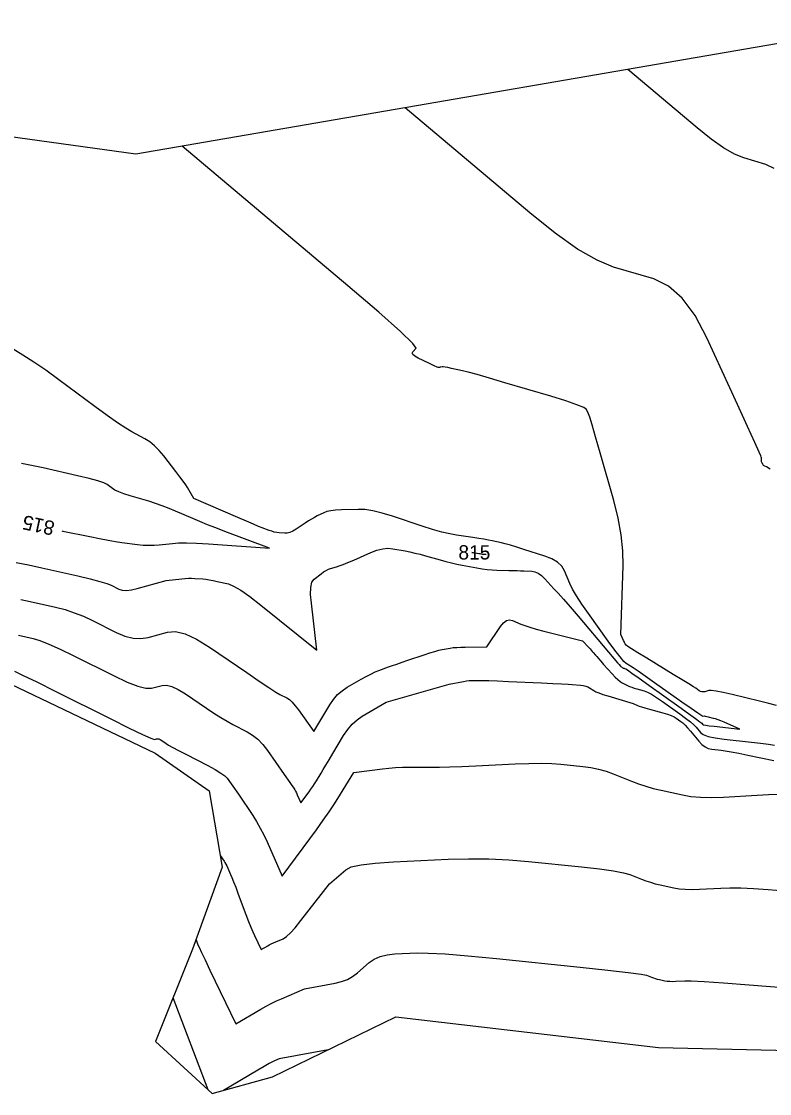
# Model space of a CAD drawing. Extents: x 1715724 to 1716561, y 394063 to 395906.
# Drawn here: x 1716062.2 to 1716135.4, y 394616.2 to 394721.1 of the extents above; entities that cross this region are included whole.
import ezdxf

# ---------------------------------------------------------------- set-up
doc = ezdxf.new("R2010")
doc.units = 0
for name, color, linetype in [('DT_X_Contour_Major', 7, 'Continuous'), ('DT_X_Contour_Minor', 7, 'Continuous'), ('DT_X_TIN_Hull', 7, 'Continuous')]:
    doc.layers.add(name, color=color, linetype=linetype)

msp = doc.modelspace()

# ---------------------------------------------------------------- linework, layer by layer
at = {"layer": 'DT_X_Contour_Major'}
for points in [[(1716066.17, 394671.24), (1716066.28, 394671.22), (1716068.92, 394670.67), (1716069.86, 394670.48), (1716070.7, 394670.32), (1716071.43, 394670.19), (1716072.05, 394670.1), (1716073.58, 394669.9), (1716074.15, 394669.85), (1716074.69, 394669.82), (1716075.21, 394669.83), (1716075.71, 394669.86), (1716077.01, 394670.01), (1716077.59, 394670.05), (1716078.38, 394670.05), (1716079.36, 394670.02), (1716080.54, 394669.95), (1716086.5, 394669.55), (1716082.14, 394671.18), (1716081.24, 394671.52), (1716080.42, 394671.84), (1716079.67, 394672.14), (1716079, 394672.43), (1716077.31, 394673.17), (1716076.67, 394673.43), (1716076.01, 394673.68), (1716075.35, 394673.91), (1716074.68, 394674.13), (1716072.87, 394674.67), (1716072.25, 394674.87), (1716071.76, 394675.05), (1716071.38, 394675.22), (1716071.13, 394675.37), (1716070.62, 394675.76), (1716070.3, 394675.92), (1716069.71, 394676.12), (1716068.85, 394676.35), (1716067.72, 394676.62), (1716064.37, 394677.39), (1716063.21, 394677.64), (1716062.22, 394677.84)], [(1716106.3, 394669.13), (1716107.23, 394668.99), (1716107.44, 394668.96), (1716107.5, 394668.95), (1716107.7, 394668.91), (1716107.51, 394668.91), (1716107.47, 394668.91), (1716107.44, 394668.91), (1716107.42, 394668.91), (1716107.4, 394668.92), (1716107.38, 394668.92), (1716107.37, 394668.92), (1716107.36, 394668.93), (1716107.35, 394668.93), (1716107.34, 394668.93), (1716107.31, 394668.94), (1716107.28, 394668.94), (1716107.22, 394668.96), (1716107.12, 394668.97), (1716106.99, 394669), (1716106.3, 394669.13)], [(1716081.68, 394639.46), (1716082.05, 394638.91), (1716082.14, 394638.78), (1716082.22, 394638.62), (1716082.32, 394638.43), (1716082.42, 394638.21), (1716082.69, 394637.6), (1716082.81, 394637.31), (1716082.98, 394636.89), (1716083.19, 394636.34), (1716083.44, 394635.66), (1716084.18, 394633.69), (1716084.44, 394633.01), (1716084.67, 394632.44), (1716084.86, 394631.97), (1716085.02, 394631.62), (1716085.69, 394630.24), (1716086.33, 394630.62), (1716086.48, 394630.7), (1716086.67, 394630.8), (1716086.88, 394630.9), (1716087.13, 394631.01), (1716087.84, 394631.31), (1716088.15, 394631.51), (1716088.54, 394631.87), (1716089.01, 394632.39), (1716089.57, 394633.08), (1716092.37, 394636.68), (1716093.95, 394638.06), (1716094.49, 394638.33), (1716095.46, 394638.55), (1716096.84, 394638.72), (1716098.63, 394638.84), (1716103.97, 394639.09), (1716105.96, 394639.14), (1716107.94, 394639.13), (1716109.91, 394639.04), (1716111.85, 394638.87), (1716117.02, 394638.34), (1716118.77, 394638.15), (1716120.14, 394637.96), (1716121.14, 394637.77), (1716121.75, 394637.6), (1716122.88, 394637.14), (1716123.32, 394636.97), (1716123.77, 394636.83), (1716124.24, 394636.69), (1716124.72, 394636.58), (1716126.04, 394636.29), (1716126.57, 394636.2), (1716127.17, 394636.15), (1716127.84, 394636.13), (1716128.58, 394636.16), (1716130.66, 394636.27), (1716131.54, 394636.3), (1716132.6, 394636.28), (1716133.85, 394636.22), (1716135.28, 394636.12), (1716139.36, 394635.8)]]:
    msp.add_lwpolyline(points, dxfattribs=at)
at = {"layer": 'DT_X_Contour_Minor'}
for points in [[(1716135.87, 394706.72), (1716135.07, 394707.11), (1716132.89, 394707.76), (1716131.99, 394708.12), (1716130.93, 394708.73), (1716129.72, 394709.59), (1716128.34, 394710.69), (1716121.56, 394716.41)], [(1716135.47, 394677.28), (1716135.11, 394677.5), (1716134.95, 394677.57), (1716134.89, 394677.6), (1716134.84, 394677.64), (1716134.8, 394677.69), (1716134.77, 394677.74), (1716134.69, 394677.89), (1716134.66, 394677.94), (1716134.64, 394678), (1716134.63, 394678.05), (1716134.63, 394678.1), (1716134.63, 394678.24), (1716134.63, 394678.29), (1716134.63, 394678.35), (1716134.62, 394678.4), (1716134.6, 394678.45), (1716134.56, 394678.59), (1716134.41, 394678.94), (1716133.98, 394679.89), (1716133.27, 394681.44), (1716132.29, 394683.59), (1716129.3, 394690.12), (1716128.13, 394692.31), (1716126.87, 394694.01), (1716125.53, 394695.2), (1716124.1, 394695.89), (1716120.15, 394697.06), (1716118.54, 394697.72), (1716116.63, 394698.82), (1716114.44, 394700.37), (1716111.97, 394702.35), (1716099.76, 394712.66)], [(1716136.1, 394654.14), (1716135.35, 394654.34), (1716134.44, 394654.57), (1716131.76, 394655.21), (1716130.87, 394655.42), (1716130.19, 394655.55), (1716129.72, 394655.61), (1716129.47, 394655.61), (1716129.08, 394655.49), (1716128.94, 394655.47), (1716128.8, 394655.47), (1716128.67, 394655.51), (1716128.54, 394655.58), (1716128.2, 394655.82), (1716127.97, 394655.97), (1716127.53, 394656.25), (1716126.87, 394656.65), (1716126, 394657.18), (1716123.4, 394658.76), (1716122.54, 394659.29), (1716121.92, 394659.68), (1716121.54, 394659.93), (1716121.38, 394660.04), (1716121.3, 394660.16), (1716121.26, 394660.22), (1716121.22, 394660.29), (1716121.18, 394660.39), (1716121.13, 394660.51), (1716120.88, 394661.1), (1716121.09, 394667.8), (1716121.07, 394669.28), (1716120.91, 394670.84), (1716120.61, 394672.47), (1716120.18, 394674.19), (1716118.85, 394678.88), (1716118.4, 394680.44), (1716118.06, 394681.6), (1716117.83, 394682.35), (1716117.71, 394682.7), (1716117.52, 394683.1), (1716117.25, 394683.3), (1716116.58, 394683.58), (1716115.5, 394683.95), (1716114.02, 394684.41), (1716109.53, 394685.74), (1716108.01, 394686.19), (1716106.81, 394686.53), (1716105.93, 394686.77), (1716105.37, 394686.91), (1716104.31, 394687.14), (1716103.96, 394687.22), (1716103.69, 394687.27), (1716103.5, 394687.29), (1716103.39, 394687.29), (1716103.21, 394687.25), (1716103.15, 394687.23), (1716103.1, 394687.23), (1716103.05, 394687.23), (1716103.01, 394687.24), (1716102.91, 394687.26), (1716102.83, 394687.3), (1716102.67, 394687.37), (1716102.41, 394687.49), (1716102.07, 394687.65), (1716101.05, 394688.15), (1716100.73, 394688.33), (1716100.53, 394688.49), (1716100.47, 394688.64), (1716100.53, 394688.77), (1716100.86, 394689.11), (1716100.53, 394689.58), (1716099.31, 394690.76), (1716097.18, 394692.64), (1716094.16, 394695.22), (1716077.95, 394708.9)], [(1716061.71, 394668.14), (1716062.93, 394667.91), (1716064.22, 394667.63), (1716067.76, 394666.82), (1716068.96, 394666.53), (1716069.9, 394666.29), (1716070.58, 394666.09), (1716071, 394665.92), (1716071.76, 394665.54), (1716072.09, 394665.43), (1716072.5, 394665.41), (1716072.99, 394665.46), (1716073.55, 394665.59), (1716076.38, 394666.37), (1716077.93, 394666.55), (1716078.26, 394666.58), (1716078.57, 394666.59), (1716078.88, 394666.59), (1716079.18, 394666.58), (1716079.96, 394666.53), (1716080.27, 394666.5), (1716080.6, 394666.45), (1716080.97, 394666.38), (1716081.37, 394666.29), (1716082.48, 394666.04), (1716082.99, 394665.83), (1716083.69, 394665.42), (1716084.58, 394664.8), (1716085.66, 394663.96), (1716091.14, 394659.57), (1716090.59, 394664.14), (1716090.51, 394665.02), (1716090.54, 394665.7), (1716090.65, 394666.2), (1716090.86, 394666.5), (1716091.54, 394667.04), (1716091.79, 394667.22), (1716092.03, 394667.37), (1716092.26, 394667.48), (1716092.48, 394667.56), (1716093.06, 394667.71), (1716093.32, 394667.8), (1716093.69, 394667.94), (1716094.16, 394668.13), (1716094.74, 394668.38), (1716096.4, 394669.11), (1716097.01, 394669.34), (1716097.57, 394669.48), (1716098.09, 394669.53), (1716098.56, 394669.49), (1716099.77, 394669.27), (1716100.24, 394669.17), (1716100.73, 394669.06), (1716101.23, 394668.94), (1716101.77, 394668.8), (1716103.21, 394668.39), (1716103.75, 394668.25), (1716104.29, 394668.12), (1716104.83, 394667.99), (1716105.36, 394667.89), (1716106.78, 394667.61), (1716107.3, 394667.52), (1716107.8, 394667.45), (1716108.28, 394667.41), (1716108.73, 394667.39), (1716109.91, 394667.36), (1716110.33, 394667.36), (1716110.72, 394667.35), (1716111.07, 394667.33), (1716111.38, 394667.32), (1716112.17, 394667.28), (1716112.47, 394667.22), (1716112.78, 394667.08), (1716113.1, 394666.85), (1716113.43, 394666.53), (1716114.33, 394665.57), (1716114.73, 394665.13), (1716115.26, 394664.54), (1716115.91, 394663.79), (1716116.68, 394662.88), (1716119.66, 394659.37), (1716120.2, 394658.73), (1716120.55, 394658.33), (1716120.7, 394658.15), (1716120.83, 394658), (1716120.88, 394657.95), (1716120.92, 394657.91), (1716120.96, 394657.88), (1716121, 394657.86), (1716121.08, 394657.82), (1716121.11, 394657.8), (1716121.19, 394657.78), (1716121.23, 394657.76), (1716121.35, 394657.73), (1716121.52, 394657.62), (1716121.96, 394657.32), (1716122.66, 394656.83), (1716123.62, 394656.14), (1716126.53, 394654.05), (1716127.49, 394653.35), (1716128.18, 394652.85), (1716128.61, 394652.53), (1716128.78, 394652.4), (1716128.86, 394652.3), (1716128.95, 394652.26), (1716129.17, 394652.22), (1716129.52, 394652.16), (1716130, 394652.11), (1716132.52, 394651.82), (1716130.97, 394652.5), (1716130.66, 394652.63), (1716130.38, 394652.74), (1716130.14, 394652.82), (1716129.94, 394652.88), (1716129.44, 394653), (1716129.27, 394653.04), (1716129.14, 394653.07), (1716129.05, 394653.08), (1716129.01, 394653.08), (1716128.93, 394653.05), (1716128.78, 394653.14), (1716128.39, 394653.4), (1716127.74, 394653.84), (1716126.85, 394654.47), (1716124.15, 394656.37), (1716123.25, 394657.01), (1716122.56, 394657.49), (1716122.08, 394657.82), (1716121.81, 394658), (1716121.39, 394658.25), (1716121.16, 394658.46), (1716120.79, 394658.9), (1716120.28, 394659.56), (1716119.63, 394660.45), (1716117.71, 394663.13), (1716117.06, 394664.06), (1716116.54, 394664.87), (1716116.15, 394665.54), (1716115.88, 394666.07), (1716115.36, 394667.33), (1716115.09, 394667.77), (1716114.68, 394668.16), (1716114.13, 394668.49), (1716113.43, 394668.77), (1716111.39, 394669.42), (1716110.68, 394669.65), (1716110.07, 394669.83), (1716109.57, 394669.97), (1716109.18, 394670.06), (1716108.28, 394670.26), (1716107.91, 394670.33), (1716107.48, 394670.41), (1716106.97, 394670.49), (1716106.4, 394670.57), (1716104.79, 394670.81), (1716104.13, 394670.93), (1716103.35, 394671.12), (1716102.44, 394671.37), (1716101.42, 394671.7), (1716098.54, 394672.66), (1716097.52, 394672.97), (1716096.61, 394673.18), (1716095.83, 394673.31), (1716095.16, 394673.34), (1716093.53, 394673.29), (1716092.97, 394673.26), (1716092.49, 394673.2), (1716092.11, 394673.12), (1716091.81, 394673.01), (1716091.15, 394672.69), (1716090.89, 394672.55), (1716090.61, 394672.39), (1716090.31, 394672.21), (1716089.99, 394672), (1716089.11, 394671.41), (1716088.79, 394671.22), (1716088.5, 394671.09), (1716088.24, 394671.01), (1716088.01, 394671), (1716087.43, 394671.05), (1716087.2, 394671.07), (1716086.97, 394671.12), (1716086.72, 394671.19), (1716086.47, 394671.27), (1716085.77, 394671.53), (1716085.43, 394671.67), (1716084.92, 394671.88), (1716084.25, 394672.17), (1716083.41, 394672.53), (1716079.1, 394674.41), (1716078.48, 394675.47), (1716078.31, 394675.74), (1716078.06, 394676.09), (1716077.73, 394676.53), (1716077.33, 394677.06), (1716076.16, 394678.58), (1716075.71, 394679.11), (1716075.26, 394679.56), (1716074.79, 394679.94), (1716074.31, 394680.24), (1716073.02, 394680.93), (1716072.43, 394681.28), (1716071.63, 394681.81), (1716070.62, 394682.52), (1716069.4, 394683.41), (1716065.88, 394686.03), (1716064.61, 394686.95), (1716063.44, 394687.75), (1716062.38, 394688.44), (1716061.43, 394689.01)], [(1716062.18, 394664.53), (1716063.09, 394664.33), (1716065.57, 394663.76), (1716066.49, 394663.52), (1716067.4, 394663.22), (1716068.3, 394662.87), (1716069.18, 394662.46), (1716071.5, 394661.3), (1716072.35, 394660.94), (1716073.16, 394660.74), (1716073.92, 394660.7), (1716074.64, 394660.81), (1716076.51, 394661.33), (1716077.29, 394661.39), (1716078.24, 394661.16), (1716079.35, 394660.64), (1716080.63, 394659.85), (1716084.27, 394657.36), (1716085.49, 394656.52), (1716086.44, 394655.89), (1716087.11, 394655.46), (1716087.5, 394655.23), (1716088.18, 394654.88), (1716088.44, 394654.71), (1716088.72, 394654.45), (1716089.01, 394654.12), (1716089.32, 394653.71), (1716090.82, 394651.59), (1716092.39, 394654.21), (1716092.75, 394654.73), (1716093.16, 394655.2), (1716093.6, 394655.59), (1716094.1, 394655.92), (1716095.47, 394656.71), (1716095.96, 394656.99), (1716096.41, 394657.22), (1716096.83, 394657.42), (1716097.2, 394657.57), (1716098.14, 394657.91), (1716098.52, 394658.05), (1716098.97, 394658.2), (1716099.47, 394658.38), (1716100.04, 394658.57), (1716101.63, 394659.11), (1716102.19, 394659.3), (1716102.67, 394659.44), (1716103.08, 394659.55), (1716103.4, 394659.62), (1716104.17, 394659.76), (1716104.48, 394659.8), (1716104.82, 394659.83), (1716105.21, 394659.85), (1716105.64, 394659.86), (1716107.75, 394659.87), (1716109.09, 394661.88), (1716109.38, 394662.24), (1716109.67, 394662.46), (1716109.97, 394662.54), (1716110.28, 394662.47), (1716111.1, 394662.11), (1716111.48, 394661.96), (1716111.97, 394661.8), (1716112.6, 394661.62), (1716113.34, 394661.42), (1716117.13, 394660.46), (1716117.73, 394659.81), (1716117.86, 394659.68), (1716117.97, 394659.55), (1716118.07, 394659.44), (1716118.16, 394659.33), (1716118.39, 394659.06), (1716118.51, 394658.93), (1716118.68, 394658.74), (1716118.9, 394658.48), (1716119.18, 394658.16), (1716120.01, 394657.23), (1716120.3, 394656.92), (1716120.57, 394656.67), (1716120.81, 394656.48), (1716121.01, 394656.35), (1716121.53, 394656.1), (1716121.73, 394656.01), (1716121.96, 394655.93), (1716122.19, 394655.85), (1716122.45, 394655.77), (1716123.16, 394655.58), (1716123.47, 394655.46), (1716123.87, 394655.24), (1716124.37, 394654.93), (1716124.95, 394654.52), (1716126.64, 394653.31), (1716127.21, 394652.89), (1716127.67, 394652.53), (1716128.01, 394652.24), (1716128.23, 394652.01), (1716128.67, 394651.48), (1716128.94, 394651.29), (1716129.42, 394651.12), (1716130.1, 394650.98), (1716130.99, 394650.85), (1716133.64, 394650.55), (1716134.55, 394650.45), (1716135.31, 394650.35), (1716135.92, 394650.26)], [(1716061.95, 394661.03), (1716063.38, 394660.7), (1716064.03, 394660.5), (1716064.91, 394660.15), (1716066.02, 394659.65), (1716067.36, 394659), (1716071.24, 394657.06), (1716072.56, 394656.43), (1716073.62, 394656.02), (1716074.41, 394655.82), (1716074.94, 394655.82), (1716075.98, 394656.11), (1716076.42, 394656.14), (1716076.95, 394656.01), (1716077.57, 394655.72), (1716078.29, 394655.28), (1716080.32, 394653.88), (1716081.06, 394653.39), (1716081.73, 394652.96), (1716082.35, 394652.6), (1716082.91, 394652.29), (1716084.32, 394651.56), (1716084.84, 394651.25), (1716085.35, 394650.83), (1716085.83, 394650.32), (1716086.3, 394649.72), (1716087.93, 394647.4), (1716088.48, 394646.61), (1716088.62, 394646.41), (1716088.87, 394646.04), (1716088.97, 394645.89), (1716089.05, 394645.74), (1716089.14, 394645.58), (1716089.22, 394645.41), (1716089.57, 394644.6), (1716090.38, 394645.7), (1716090.55, 394645.94), (1716090.73, 394646.2), (1716090.9, 394646.47), (1716091.08, 394646.75), (1716091.55, 394647.53), (1716091.76, 394647.87), (1716092.01, 394648.3), (1716092.33, 394648.82), (1716092.7, 394649.43), (1716093.75, 394651.19), (1716094.16, 394651.8), (1716094.6, 394652.32), (1716095.07, 394652.75), (1716095.56, 394653.09), (1716097.92, 394654.45), (1716104.09, 394656.24), (1716105.49, 394656.49), (1716105.77, 394656.54), (1716106.04, 394656.57), (1716106.28, 394656.59), (1716106.5, 394656.6), (1716107.05, 394656.6), (1716107.39, 394656.59), (1716107.97, 394656.58), (1716108.8, 394656.54), (1716109.89, 394656.49), (1716113.11, 394656.35), (1716114.21, 394656.3), (1716115.07, 394656.26), (1716115.71, 394656.22), (1716116.12, 394656.19), (1716116.92, 394656.12), (1716117.2, 394656.09), (1716117.44, 394656.04), (1716117.65, 394655.96), (1716117.82, 394655.87), (1716118.22, 394655.6), (1716118.42, 394655.49), (1716118.72, 394655.37), (1716119.11, 394655.23), (1716119.59, 394655.08), (1716122.09, 394654.34), (1716122.51, 394654.13), (1716122.65, 394654.08), (1716122.89, 394654), (1716123.23, 394653.9), (1716123.67, 394653.78), (1716124.97, 394653.42), (1716125.42, 394653.29), (1716125.79, 394653.16), (1716126.08, 394653.03), (1716126.29, 394652.91), (1716126.74, 394652.58), (1716126.93, 394652.43), (1716127.15, 394652.21), (1716127.4, 394651.94), (1716127.68, 394651.61), (1716128.49, 394650.65), (1716128.79, 394650.33), (1716129.11, 394650.09), (1716129.43, 394649.93), (1716129.77, 394649.85), (1716130.67, 394649.75), (1716131.09, 394649.69), (1716131.67, 394649.59), (1716132.4, 394649.46), (1716133.28, 394649.28), (1716135.85, 394648.77)], [(1716061.56, 394657.49), (1716062.41, 394657.09), (1716063.74, 394656.44), (1716065.54, 394655.54), (1716070.98, 394652.82), (1716072.78, 394651.93), (1716074.08, 394651.3), (1716074.9, 394650.93), (1716075.23, 394650.82), (1716075.45, 394650.89), (1716075.55, 394650.89), (1716075.66, 394650.87), (1716075.79, 394650.8), (1716075.95, 394650.71), (1716076.38, 394650.41), (1716076.62, 394650.26), (1716077.03, 394650.04), (1716077.59, 394649.73), (1716078.32, 394649.36), (1716080.47, 394648.25), (1716081.19, 394647.86), (1716081.75, 394647.53), (1716082.14, 394647.25), (1716082.37, 394647.02), (1716082.75, 394646.48), (1716082.92, 394646.23), (1716083.46, 394645.45), (1716084.86, 394643.37), (1716085.24, 394642.77), (1716085.6, 394642.14), (1716085.95, 394641.48), (1716086.27, 394640.78), (1716087.75, 394637.44), (1716091.08, 394641.98), (1716091.75, 394642.9), (1716092.32, 394643.72), (1716092.8, 394644.43), (1716093.18, 394645.03), (1716094.74, 394647.59), (1716097.54, 394647.95), (1716098.16, 394648.02), (1716098.82, 394648.06), (1716099.52, 394648.09), (1716100.26, 394648.1), (1716102.29, 394648.11), (1716103.13, 394648.11), (1716104.14, 394648.14), (1716105.33, 394648.18), (1716106.68, 394648.24), (1716110.52, 394648.42), (1716111.88, 394648.47), (1716113.08, 394648.48), (1716114.12, 394648.45), (1716115.01, 394648.39), (1716117.15, 394648.16), (1716117.94, 394648.06), (1716118.7, 394647.9), (1716119.42, 394647.7), (1716120.11, 394647.45), (1716121.9, 394646.73), (1716122.59, 394646.47), (1716123.3, 394646.23), (1716124.04, 394646.02), (1716124.8, 394645.84), (1716126.89, 394645.38), (1716127.72, 394645.24), (1716128.67, 394645.16), (1716129.74, 394645.14), (1716130.92, 394645.18), (1716134.21, 394645.36), (1716135.32, 394645.42), (1716136.18, 394645.45)], [(1716079.31, 394631.21), (1716079.5, 394630.7), (1716079.6, 394630.47), (1716079.83, 394629.97), (1716080.19, 394629.23), (1716080.67, 394628.23), (1716083.21, 394622.97), (1716085.65, 394624.41), (1716086.16, 394624.71), (1716086.67, 394624.98), (1716087.17, 394625.22), (1716087.66, 394625.44), (1716089.91, 394626.41), (1716092.93, 394626.96), (1716093.55, 394627.11), (1716094.12, 394627.32), (1716094.63, 394627.61), (1716095.1, 394627.96), (1716096.26, 394628.98), (1716096.75, 394629.32), (1716097.32, 394629.57), (1716098, 394629.74), (1716098.76, 394629.82), (1716100.93, 394629.92), (1716102.02, 394629.91), (1716103.68, 394629.82), (1716105.91, 394629.63), (1716108.7, 394629.36), (1716116.89, 394628.52), (1716119.6, 394628.23), (1716121.59, 394628.01), (1716122.85, 394627.84), (1716123.39, 394627.74), (1716123.87, 394627.55), (1716124.05, 394627.48), (1716124.24, 394627.42), (1716124.43, 394627.36), (1716124.64, 394627.32), (1716125.19, 394627.19), (1716125.41, 394627.16), (1716125.66, 394627.14), (1716125.94, 394627.13), (1716126.25, 394627.14), (1716127.12, 394627.19), (1716127.76, 394627.18), (1716129.02, 394627.11), (1716130.9, 394626.98), (1716133.41, 394626.79), (1716140.92, 394626.2)], [(1716080.49, 394616.52), (1716077.07, 394625.53)], [(1716092.24, 394620.43), (1716087.45, 394619.56), (1716086.98, 394619.36), (1716086.8, 394619.27), (1716086.47, 394619.09), (1716085.99, 394618.81), (1716085.35, 394618.43), (1716082.01, 394616.46)]]:
    msp.add_lwpolyline(points, dxfattribs=at)
at = {"layer": 'DT_X_TIN_Hull'}
for points in [[(1716148.77, 394721.1), (1716073.41, 394708.12), (1716044.16, 394712.17)], [(1716060.43, 394656.59), (1716075.31, 394649.47), (1716080.58, 394645.79), (1716081.88, 394638.32), (1716078.97, 394630.28), (1716075.35, 394621.25), (1716080.89, 394616.15), (1716086.8, 394617.78), (1716098.85, 394623.66), (1716124.57, 394620.66), (1716148.93, 394620.11)]]:
    msp.add_lwpolyline(points, dxfattribs=at)

# ---------------------------------------------------------------- texts
at = {"layer": 'DT_X_Contour_Major'}
msp.add_text('815', height=1.4, rotation=167.8609, dxfattribs=at).set_placement((1716065.57, 394672.13))
msp.add_text('815', height=1.4, dxfattribs=at).set_placement((1716104.98, 394668.43))

doc.saveas('drawing.dxf')
